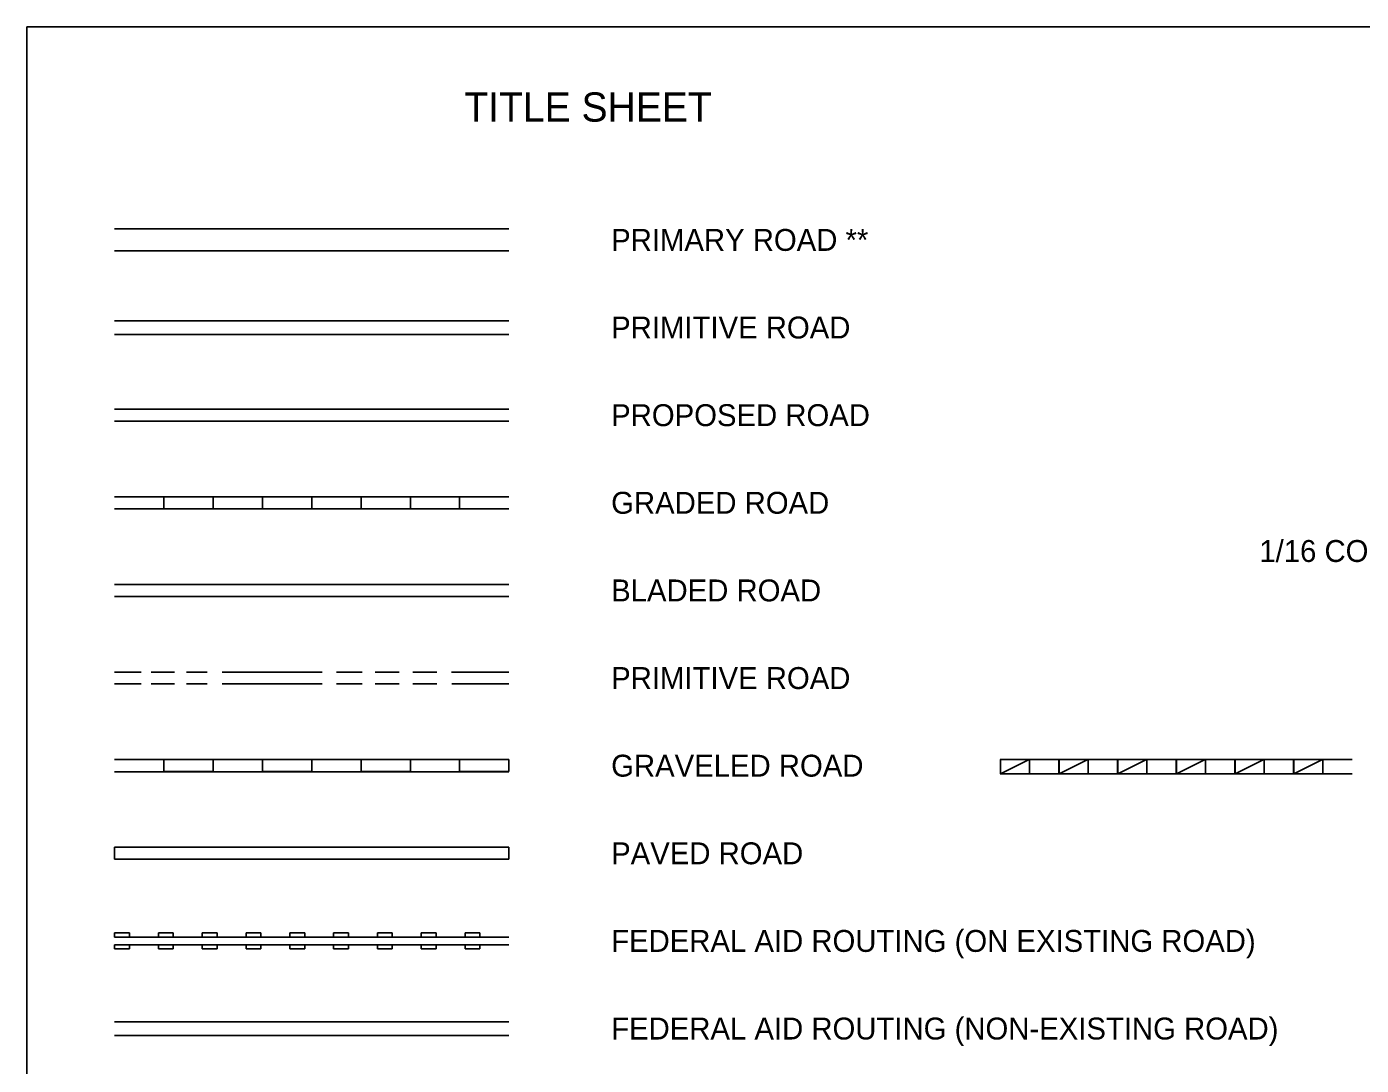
# Model space of a CAD drawing. Extents: x 49991.4 to 50021, y 49987.6 to 50011.4.
# Drawn here: x 49999.384 to 50003.039, y 49996.155 to 49998.999 of the extents above; entities that cross this region are included whole.
import ezdxf

# ---------------------------------------------------------------- set-up
doc = ezdxf.new("R2010")
doc.units = 0
doc.layers.add('Level 1', color=7, linetype='Continuous')
doc.layers.add('Level 2', color=7, linetype='Continuous')

msp = doc.modelspace()

# ---------------------------------------------------------------- linework, layer by layer
at = {"layer": 'Level 1'}
for p, q in [((49999.6243, 49998.4452), (50000.7043, 49998.4452)), ((49999.6243, 49998.3852), (50000.7043, 49998.3852)), ((49999.6243, 49998.194), (50000.7043, 49998.194)), ((49999.6243, 49998.1565), (50000.7043, 49998.1565)), ((49999.6243, 49997.9517), (50000.7043, 49997.9517)), ((49999.6243, 49997.9187), (50000.7043, 49997.9187)), ((49999.6243, 49997.9187), (50000.7043, 49997.9187)), ((49999.6243, 49997.7117), (50000.7043, 49997.7117)), ((49999.7593, 49997.7117), (49999.7593, 49997.6787)), ((49999.8943, 49997.7117), (49999.8943, 49997.6787)), ((50000.0293, 49997.7117), (50000.0293, 49997.6787)), ((50000.1643, 49997.7117), (50000.1643, 49997.6787)), ((50000.2993, 49997.7117), (50000.2993, 49997.6787)), ((50000.4343, 49997.7117), (50000.4343, 49997.6787)), ((50000.5693, 49997.7117), (50000.5693, 49997.6787)), ((49999.6243, 49997.6787), (50000.7043, 49997.6787)), ((49999.6243, 49997.4717), (50000.7043, 49997.4717)), ((49999.6243, 49997.4387), (50000.7043, 49997.4387)), ((49999.6243, 49997.2315), (49999.6967, 49997.2315)), ((49999.7245, 49997.2315), (49999.7881, 49997.2315)), ((49999.8208, 49997.2315), (49999.8779, 49997.2315)), ((49999.9187, 49997.2315), (50000.1929, 49997.2315)), ((50000.2321, 49997.2315), (50000.3023, 49997.2315)), ((50000.3382, 49997.2315), (50000.4035, 49997.2315)), ((50000.4411, 49997.2315), (50000.5064, 49997.2315)), ((50000.5469, 49997.2315), (50000.7043, 49997.2315)), ((49999.6243, 49997.199), (49999.6967, 49997.199)), ((49999.7245, 49997.199), (49999.7881, 49997.199)), ((49999.8208, 49997.199), (49999.8779, 49997.199)), ((49999.9187, 49997.199), (50000.1929, 49997.199)), ((50000.2321, 49997.199), (50000.3023, 49997.199)), ((50000.3382, 49997.199), (50000.4035, 49997.199)), ((50000.4411, 49997.199), (50000.5064, 49997.199)), ((50000.5479, 49997.199), (50000.7043, 49997.199)), ((49999.6243, 49996.9922), (50000.7043, 49996.9922)), ((49999.7593, 49996.9922), (49999.7593, 49996.9592)), ((49999.7593, 49996.9922), (49999.7593, 49996.9592)), ((49999.7593, 49996.9592), (49999.7593, 49996.9922)), ((49999.7593, 49996.9922), (49999.8943, 49996.9922)), ((49999.8943, 49996.9922), (49999.8943, 49996.9592)), ((50000.0293, 49996.9592), (50000.0293, 49996.9922)), ((50000.0293, 49996.9922), (50000.1643, 49996.9922)), ((50000.1643, 49996.9922), (50000.1643, 49996.9592)), ((50000.2993, 49996.9592), (50000.2993, 49996.9922)), ((50000.2993, 49996.9922), (50000.4343, 49996.9922)), ((50000.4343, 49996.9922), (50000.4343, 49996.9592)), ((50000.5693, 49996.9592), (50000.5693, 49996.9922)), ((50000.5693, 49996.9922), (50000.704, 49996.9922)), ((50000.704, 49996.9922), (50000.704, 49996.9592)), ((50002.0498, 49996.9922), (50003.0138, 49996.9922)), ((50002.051, 49996.9922), (50002.129, 49996.9922)), ((50002.129, 49996.9922), (50002.051, 49996.9532)), ((50002.051, 49996.9532), (50002.051, 49996.9922)), ((50002.1301, 49996.9532), (50002.1301, 49996.9922)), ((50002.2105, 49996.9532), (50002.2105, 49996.9922)), ((50002.2116, 49996.9922), (50002.2896, 49996.9922)), ((50002.2896, 49996.9922), (50002.2116, 49996.9532)), ((50002.2116, 49996.9532), (50002.2116, 49996.9922)), ((50002.2908, 49996.9532), (50002.2908, 49996.9922)), ((50002.3711, 49996.9532), (50002.3711, 49996.9922)), ((50002.3723, 49996.9922), (50002.4503, 49996.9922)), ((50002.4503, 49996.9922), (50002.3723, 49996.9532)), ((50002.3723, 49996.9532), (50002.3723, 49996.9922)), ((50002.4515, 49996.9532), (50002.4515, 49996.9922)), ((50002.5318, 49996.9532), (50002.5318, 49996.9922)), ((50002.5329, 49996.9922), (50002.6109, 49996.9922)), ((50002.6109, 49996.9922), (50002.5329, 49996.9532)), ((50002.5329, 49996.9532), (50002.5329, 49996.9922)), ((50002.6121, 49996.9532), (50002.6121, 49996.9922)), ((50002.6924, 49996.9532), (50002.6924, 49996.9922)), ((50002.6936, 49996.9922), (50002.7716, 49996.9922)), ((50002.7716, 49996.9922), (50002.6936, 49996.9532)), ((50002.6936, 49996.9532), (50002.6936, 49996.9922)), ((50002.7728, 49996.9532), (50002.7728, 49996.9922)), ((50002.8531, 49996.9532), (50002.8531, 49996.9922)), ((50002.8543, 49996.9922), (50002.9323, 49996.9922)), ((50002.9323, 49996.9922), (50002.8543, 49996.9532)), ((50002.8543, 49996.9532), (50002.8543, 49996.9922)), ((50002.9334, 49996.9532), (50002.9334, 49996.9922)), ((50000.7042, 49996.9582), (49999.6243, 49996.9582)), ((49999.8943, 49996.9592), (49999.7593, 49996.9592)), ((50000.1643, 49996.9592), (50000.0293, 49996.9592)), ((50000.4343, 49996.9592), (50000.2993, 49996.9592)), ((50000.704, 49996.9592), (50000.5693, 49996.9592)), ((50002.0498, 49996.9532), (50003.0138, 49996.9532)), ((49999.6242, 49996.7187), (49999.6242, 49996.7517)), ((49999.6243, 49996.7517), (50000.704, 49996.7517)), ((50000.704, 49996.7517), (50000.704, 49996.7187)), ((49999.6243, 49996.7187), (49999.6242, 49996.7187)), ((50000.704, 49996.7187), (49999.6243, 49996.7187)), ((49999.6649, 49996.5173), (49999.6242, 49996.5173)), ((49999.6242, 49996.5173), (49999.6242, 49996.5057)), ((49999.6242, 49996.5057), (50000.7043, 49996.5057)), ((49999.6242, 49996.5057), (49999.6649, 49996.5057)), ((49999.6649, 49996.5057), (49999.6649, 49996.5173)), ((49999.7849, 49996.5173), (49999.7442, 49996.5173)), ((49999.7442, 49996.5173), (49999.7442, 49996.5057)), ((49999.7442, 49996.5057), (49999.7849, 49996.5057)), ((49999.7849, 49996.5057), (49999.7849, 49996.5173)), ((49999.9049, 49996.5173), (49999.8642, 49996.5173)), ((49999.8642, 49996.5173), (49999.8642, 49996.5057)), ((49999.8642, 49996.5057), (49999.9049, 49996.5057)), ((49999.9049, 49996.5057), (49999.9049, 49996.5173)), ((50000.0249, 49996.5173), (49999.9842, 49996.5173)), ((49999.9842, 49996.5173), (49999.9842, 49996.5057)), ((49999.9842, 49996.5057), (50000.0249, 49996.5057)), ((50000.0249, 49996.5057), (50000.0249, 49996.5173)), ((50000.1449, 49996.5173), (50000.1042, 49996.5173)), ((50000.1042, 49996.5173), (50000.1042, 49996.5057)), ((50000.1042, 49996.5057), (50000.1449, 49996.5057)), ((50000.1449, 49996.5057), (50000.1449, 49996.5173)), ((50000.2649, 49996.5173), (50000.2242, 49996.5173)), ((50000.2242, 49996.5173), (50000.2242, 49996.5057)), ((50000.2242, 49996.5057), (50000.2649, 49996.5057)), ((50000.2649, 49996.5057), (50000.2649, 49996.5173)), ((50000.3849, 49996.5173), (50000.3442, 49996.5173)), ((50000.3442, 49996.5173), (50000.3442, 49996.5057)), ((50000.3442, 49996.5057), (50000.3849, 49996.5057)), ((50000.3849, 49996.5057), (50000.3849, 49996.5173)), ((50000.5049, 49996.5173), (50000.4642, 49996.5173)), ((50000.4642, 49996.5173), (50000.4642, 49996.5057)), ((50000.4642, 49996.5057), (50000.5049, 49996.5057)), ((50000.5049, 49996.5057), (50000.5049, 49996.5173)), ((50000.6249, 49996.5173), (50000.5842, 49996.5173)), ((50000.5842, 49996.5173), (50000.5842, 49996.5057)), ((50000.5842, 49996.5057), (50000.6249, 49996.5057)), ((50000.6249, 49996.5057), (50000.6249, 49996.5173)), ((49999.6242, 49996.4847), (50000.7043, 49996.4847)), ((49999.6649, 49996.4847), (49999.6242, 49996.4847)), ((49999.6242, 49996.4847), (49999.6242, 49996.4731)), ((49999.6242, 49996.4731), (49999.6649, 49996.4731)), ((49999.6649, 49996.4731), (49999.6649, 49996.4847)), ((49999.7849, 49996.4847), (49999.7442, 49996.4847)), ((49999.7442, 49996.4847), (49999.7442, 49996.4731)), ((49999.7442, 49996.4731), (49999.7849, 49996.4731)), ((49999.7849, 49996.4731), (49999.7849, 49996.4847)), ((49999.9049, 49996.4847), (49999.8642, 49996.4847)), ((49999.8642, 49996.4847), (49999.8642, 49996.4731)), ((49999.8642, 49996.4731), (49999.9049, 49996.4731)), ((49999.9049, 49996.4731), (49999.9049, 49996.4847)), ((50000.0249, 49996.4847), (49999.9842, 49996.4847)), ((49999.9842, 49996.4847), (49999.9842, 49996.4731)), ((49999.9842, 49996.4731), (50000.0249, 49996.4731)), ((50000.0249, 49996.4731), (50000.0249, 49996.4847)), ((50000.1449, 49996.4847), (50000.1042, 49996.4847)), ((50000.1042, 49996.4847), (50000.1042, 49996.4731)), ((50000.1042, 49996.4731), (50000.1449, 49996.4731)), ((50000.1449, 49996.4731), (50000.1449, 49996.4847)), ((50000.2649, 49996.4847), (50000.2242, 49996.4847)), ((50000.2242, 49996.4847), (50000.2242, 49996.4731)), ((50000.2242, 49996.4731), (50000.2649, 49996.4731)), ((50000.2649, 49996.4731), (50000.2649, 49996.4847)), ((50000.3849, 49996.4847), (50000.3442, 49996.4847)), ((50000.3442, 49996.4847), (50000.3442, 49996.4731)), ((50000.3442, 49996.4731), (50000.3849, 49996.4731)), ((50000.3849, 49996.4731), (50000.3849, 49996.4847)), ((50000.5049, 49996.4847), (50000.4642, 49996.4847)), ((50000.4642, 49996.4847), (50000.4642, 49996.4731)), ((50000.4642, 49996.4731), (50000.5049, 49996.4731)), ((50000.5049, 49996.4731), (50000.5049, 49996.4847)), ((50000.6249, 49996.4847), (50000.5842, 49996.4847)), ((50000.5842, 49996.4847), (50000.5842, 49996.4731)), ((50000.5842, 49996.4731), (50000.6249, 49996.4731)), ((50000.6249, 49996.4731), (50000.6249, 49996.4847)), ((49999.6243, 49996.2739), (50000.7043, 49996.2739)), ((49999.6243, 49996.2364), (50000.7043, 49996.2364))]:
    msp.add_line(p, q, dxfattribs=at)
msp.add_lwpolyline([(49999.3835, 49998.9992), (50016.7501, 49998.9992), (50016.7501, 49987.7988), (49999.3835, 49987.7988)], close=True, dxfattribs=at)

# ---------------------------------------------------------------- texts
at = {"layer": 'Level 2'}
for s, height, p in [('TITLE SHEET', 0.08, (50000.5822, 49998.7392)), ('PRIMARY ROAD **      ', 0.06, (50000.9843, 49998.3852)), ('PRIMITIVE ROAD      ', 0.059999, (50000.9843, 49998.1452)), ('PROPOSED ROAD       ', 0.059999, (50000.9843, 49997.9052)), ('GRADED ROAD         ', 0.059999, (50000.9843, 49997.6652)), ('1/16 CORNER', 0.06, (50002.7596, 49997.5332)), ('BLADED ROAD         ', 0.059999, (50000.9843, 49997.4252)), ('PRIMITIVE ROAD      ', 0.059999, (50000.9843, 49997.1852)), ('GRAVELED ROAD       ', 0.059999, (50000.9843, 49996.9452)), ('PAVED ROAD          ', 0.059999, (50000.9843, 49996.7052)), ('FEDERAL AID ROUTING (ON EXISTING ROAD)  ', 0.059999, (50000.9843, 49996.4652)), ('FEDERAL AID ROUTING (NON-EXISTING ROAD) ', 0.059999, (50000.9843, 49996.2252))]:
    msp.add_text(s, height=height, dxfattribs=at).set_placement(p)

doc.saveas('drawing.dxf')
